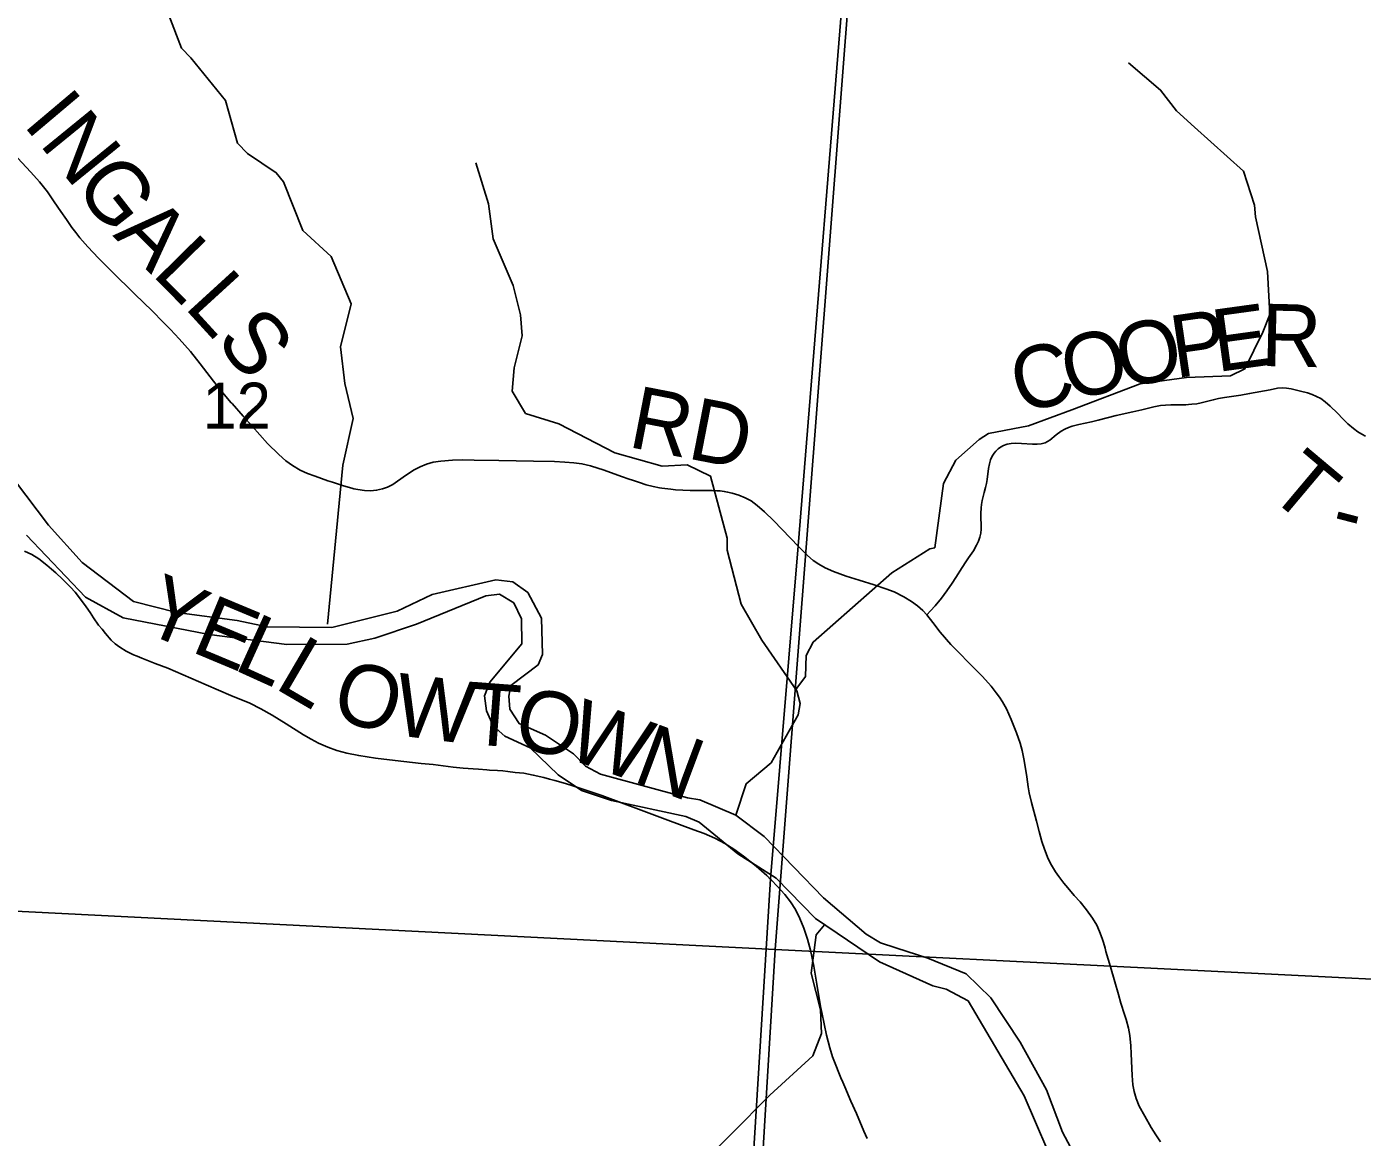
# Model space of a CAD drawing. Extents: x 396.2 to 468.4, y 232.6 to 279.1.
# Drawn here: x 420.064 to 421.28, y 275.126 to 276.138 of the extents above; entities that cross this region are included whole.
import ezdxf

# ---------------------------------------------------------------- set-up
doc = ezdxf.new("R2010")
doc.units = 0
for name, color, linetype in [('GM_X_County_Road', 7, 'Continuous'), ('GM_X_County_Road_Text', 7, 'Continuous'), ('GM_X_Major_River', 7, 'Continuous'), ('GM_X_Minor_River', 7, 'Continuous'), ('GM_X_Section', 7, 'Continuous'), ('GM_X_Section_Text', 7, 'Continuous'), ('GM_X_Township', 7, 'Continuous'), ('GM_X_Township_Road', 7, 'Continuous'), ('GM_X_Township_Road_Text', 7, 'Continuous')]:
    doc.layers.add(name, color=color, linetype=linetype)

msp = doc.modelspace()

# ---------------------------------------------------------------- linework, layer by layer
at = {"layer": 'GM_X_County_Road'}
for points in [[(420.2507, 275.7942), (420.25, 275.7949), (420.2435, 275.8024), (420.2338, 275.8145), (420.2217, 275.8303), (420.2128, 275.8415), (420.2026, 275.8532), (420.1945, 275.8617), (420.188, 275.8685), (420.1779, 275.8786), (420.1623, 275.8938), (420.141, 275.9147), (420.1292, 275.9266), (420.1194, 275.937), (420.112, 275.9453), (420.1084, 275.9501), (420.1048, 275.9546), (420.0998, 275.9618), (420.0948, 275.9691), (420.0886, 275.9781), (420.0826, 275.9871), (420.0754, 275.9962), (420.0675, 276.0051), (420.0552, 276.0182)], [(420.7664, 275.664), (420.744, 275.6874), (420.7356, 275.6957), (420.729, 275.7014), (420.7234, 275.7055), (420.7179, 275.7085), (420.7121, 275.7109), (420.7061, 275.7126), (420.7019, 275.7136), (420.6989, 275.7142), (420.6951, 275.7146), (420.6921, 275.7148), (420.6878, 275.715), (420.6853, 275.715), (420.6773, 275.7149), (420.668, 275.7149), (420.6544, 275.7157), (420.6501, 275.7161), (420.6422, 275.7172), (420.6398, 275.7176), (420.6343, 275.7187), (420.6277, 275.7203), (420.6218, 275.7222), (420.6154, 275.7243), (420.6124, 275.7253), (420.6054, 275.7279), (420.5896, 275.7336), (420.5772, 275.7376), (420.5693, 275.7394), (420.5618, 275.7403), (420.5537, 275.7408), (420.5444, 275.7413), (420.5252, 275.7419), (420.4935, 275.7424), (420.4712, 275.7427), (420.4606, 275.7429), (420.4513, 275.7427), (420.4407, 275.7419), (420.4339, 275.7408), (420.4279, 275.739), (420.4221, 275.7367), (420.4166, 275.7338), (420.4087, 275.7287), (420.3971, 275.7206), (420.3923, 275.7181), (420.3877, 275.7165), (420.3823, 275.7153), (420.3768, 275.7148), (420.3713, 275.715), (420.3653, 275.7159), (420.3616, 275.7166), (420.3599, 275.7171), (420.3521, 275.7193), (420.3421, 275.7225), (420.338, 275.7239), (420.3263, 275.728), (420.3193, 275.7306), (420.3126, 275.7337), (420.3057, 275.7377), (420.2997, 275.7421), (420.2932, 275.7478), (420.2831, 275.7579), (420.269, 275.7735), (420.2607, 275.7828), (420.2507, 275.7942)], [(421.0961, 275.1218), (421.092, 275.128), (421.0877, 275.1348), (421.0819, 275.145), (421.0768, 275.1542), (421.074, 275.1611), (421.0721, 275.1676), (421.071, 275.1736), (421.0703, 275.1822), (421.0695, 275.2019), (421.0692, 275.2093), (421.0683, 275.2186), (421.0671, 275.2253), (421.0649, 275.2331), (421.0633, 275.2378), (421.06, 275.248), (421.0578, 275.2558), (421.0545, 275.2674), (421.0506, 275.2812), (421.0465, 275.295), (421.0457, 275.298), (421.0441, 275.3032), (421.043, 275.3069), (421.0407, 275.3134), (421.0381, 275.3191), (421.0343, 275.3255), (421.0289, 275.3331), (421.023, 275.3402), (421.0176, 275.3462), (421.0147, 275.3494), (421.01, 275.3551), (421.0081, 275.3575), (421.0036, 275.3635), (421.0004, 275.3678), (420.9968, 275.3736), (420.9938, 275.3796), (420.9904, 275.3882), (420.9881, 275.3953), (420.9856, 275.4043), (420.9832, 275.4139), (420.9786, 275.4307), (420.9765, 275.4397), (420.9756, 275.4452), (420.9743, 275.4543), (420.9721, 275.4691), (420.9702, 275.4783), (420.9683, 275.4849), (420.9651, 275.4943), (420.9602, 275.5064), (420.9559, 275.5161), (420.9522, 275.5226), (420.9494, 275.5267), (420.9465, 275.5308), (420.9419, 275.5367), (420.934, 275.5455), (420.9214, 275.5584), (420.9131, 275.5668), (420.9053, 275.5748), (420.8956, 275.586), (420.8889, 275.5948), (420.8834, 275.6017), (420.8796, 275.6058), (420.8749, 275.61), (420.8694, 275.614), (420.8624, 275.6182), (420.8535, 275.6226), (420.846, 275.6256), (420.8354, 275.6292), (420.8217, 275.6333), (420.8099, 275.6371), (420.7983, 275.6414), (420.7909, 275.6447), (420.785, 275.6479), (420.7799, 275.6514), (420.7748, 275.6558), (420.7664, 275.664)]]:
    msp.add_lwpolyline(points, dxfattribs=at)
at = {"layer": 'GM_X_Major_River'}
for points in [[(420.0835, 275.6834), (420.0205, 275.7665)], [(420.8844, 275.289), (420.855, 275.2985), (420.8413, 275.3031), (420.8281, 275.311), (420.7894, 275.3439), (420.7351, 275.3998), (420.7094, 275.4194), (420.6768, 275.4334), (420.6654, 275.4352), (420.5863, 275.4566), (420.5726, 275.4638), (420.5616, 275.4751), (420.5362, 275.4921), (420.512, 275.5027), (420.5036, 275.5159), (420.5028, 275.5277), (420.5047, 275.5375), (420.5293, 275.5562), (420.5334, 275.5657), (420.5326, 275.5986), (420.52, 275.6221), (420.5064, 275.6319), (420.4909, 275.6338), (420.433, 275.6203), (420.4009, 275.6051), (420.3415, 275.5901), (420.2828, 275.5907), (420.2552, 275.5967), (420.2003, 275.6038), (420.1609, 275.6139), (420.1142, 275.6494), (420.0835, 275.6834)], [(420.0635, 275.6743), (420.1173, 275.6179), (420.1514, 275.5991), (420.2298, 275.5838), (420.3006, 275.5749), (420.3555, 275.575), (420.3808, 275.5804), (420.4187, 275.5934), (420.4818, 275.619), (420.4943, 275.6205), (420.5072, 275.6126), (420.5144, 275.5982), (420.5145, 275.5755), (420.4854, 275.5405), (420.4805, 275.528), (420.4824, 275.5143), (420.4885, 275.5007), (420.4991, 275.4913), (420.5222, 275.4807), (420.5477, 275.4561), (420.5689, 275.4418), (420.5962, 275.4328), (420.6639, 275.4182), (420.6761, 275.4129), (420.7113, 275.3842), (420.7462, 275.3619), (420.7819, 275.3253), (420.8402, 275.2856), (420.8887, 275.2638), (420.9009, 275.2609)], [(421.0288, 275.0896), (421.007, 275.1305), (420.9924, 275.1691), (420.9684, 275.2126), (420.9417, 275.253), (420.9193, 275.2748), (420.8844, 275.289)], [(420.9009, 275.2609), (420.9209, 275.2502), (420.972, 275.1636), (421.0038, 275.0895)]]:
    msp.add_lwpolyline(points, dxfattribs=at)
at = {"layer": 'GM_X_Minor_River'}
for points in [[(420.3377, 275.5934), (420.3515, 275.738), (420.361, 275.7806), (420.3535, 275.8125), (420.3493, 275.846), (420.3592, 275.8852), (420.341, 275.9281), (420.3152, 275.952), (420.2974, 275.9961), (420.291, 276.0045), (420.2648, 276.0219), (420.2557, 276.0314), (420.2448, 276.0702), (420.2133, 276.109), (420.2046, 276.1181), (420.1932, 276.1481)], [(420.8906, 275.6629), (420.8985, 275.7215), (420.9099, 275.7428), (420.9311, 275.7614), (420.9395, 275.7671), (420.9759, 275.774), (421.0153, 275.7885), (421.0775, 275.8121), (421.1199, 275.8179), (421.1598, 275.8195), (421.173, 275.8259), (421.1893, 275.8594), (421.1958, 275.8754), (421.1935, 275.9145), (421.1826, 275.9643), (421.1818, 275.975), (421.1716, 276.0058), (421.1272, 276.046), (421.1106, 276.0608), (421.0962, 276.0798), (421.067, 276.1045)], [(420.7015, 275.6715), (420.6863, 275.7281), (420.665, 275.7383), (420.6423, 275.7372), (420.5994, 275.7493), (420.5483, 275.7759), (420.518, 275.7853), (420.5058, 275.8055), (420.5077, 275.8268), (420.515, 275.856), (420.5134, 275.8751), (420.5066, 275.9017), (420.4885, 275.9442), (420.4843, 275.9762), (420.4726, 276.0134)], [(420.7015, 275.6715), (420.7016, 275.6608), (420.7144, 275.6115), (420.7332, 275.5786), (420.765, 275.5324), (420.7681, 275.521), (420.7663, 275.5108), (420.7415, 275.467), (420.7188, 275.4479), (420.7094, 275.4194)], [(420.7641, 275.5337), (420.7729, 275.5457), (420.7735, 275.5647), (420.7799, 275.5769), (420.8516, 275.6399), (420.886, 275.6618), (420.8906, 275.6629)], [(420.7901, 275.3195), (420.7827, 275.3104), (420.778, 275.2754), (420.7865, 275.242), (420.7874, 275.2204), (420.7796, 275.2002), (420.7403, 275.1643), (420.6705, 275.0937), (420.6055, 275.0482), (420.5546, 275.0039)]]:
    msp.add_lwpolyline(points, dxfattribs=at)
at = {"layer": 'GM_X_Section'}
for points in [[(419.7599, 276.357), (420.8122, 276.3213), (420.8243, 276.321), (420.7452, 275.2968), (419.7043, 275.3495)], [(420.8243, 276.321), (421.8725, 276.2694), (421.8607, 276.0303), (421.8429, 275.7758), (421.8262, 275.5154), (421.8083, 275.2473), (421.8081, 275.2441), (420.7452, 275.2968)], [(419.7043, 275.3495), (420.7452, 275.2968), (420.6845, 274.2907), (419.6431, 274.3525)], [(420.7452, 275.2968), (421.8081, 275.2441), (421.7928, 275.0058), (421.7775, 274.755), (421.761, 274.4956), (421.7452, 274.2485), (420.6845, 274.2907)]]:
    msp.add_lwpolyline(points, close=True, dxfattribs=at)
at = {"layer": 'GM_X_Township'}
for points in [[(418.0397, 276.4561), (419.5043, 276.3698), (419.7967, 276.3558), (420.5319, 276.3287), (420.82, 276.3196), (420.8133, 276.2466), (420.7662, 275.6645), (420.7409, 275.3613), (420.6691, 274.1958), (420.5899, 272.7669), (420.561, 272.2781), (420.5108, 271.2751)], [(420.6691, 274.1958), (420.7409, 275.3613), (420.7662, 275.6645), (420.8133, 276.2466), (420.82, 276.3196), (421.3281, 276.2897)]]:
    msp.add_lwpolyline(points, dxfattribs=at)
at = {"layer": 'GM_X_Township_Road'}
for points in [[(420.8834, 275.6017), (420.8868, 275.6053), (420.8909, 275.6099), (420.8968, 275.6171), (420.9016, 275.6235), (420.9065, 275.6307), (420.9099, 275.6359), (420.9155, 275.6448), (420.9189, 275.65), (420.9214, 275.6536), (420.9259, 275.6602), (420.9287, 275.6651), (420.9305, 275.669), (420.9317, 275.6725), (420.9324, 275.6762), (420.9327, 275.6799), (420.9326, 275.6941), (420.9329, 275.6991), (420.9332, 275.7022), (420.9339, 275.7058), (420.9344, 275.7083), (420.9356, 275.7131), (420.9369, 275.7179), (420.9377, 275.7215), (420.9384, 275.7252), (420.9396, 275.7351), (420.9404, 275.7393), (420.9414, 275.7429), (420.943, 275.7463), (420.9446, 275.7489), (420.9462, 275.7509), (420.9484, 275.753), (420.9504, 275.7545), (420.9531, 275.7559), (420.9566, 275.7572), (420.9603, 275.7578), (420.964, 275.758), (420.9696, 275.7578), (420.9795, 275.7571), (420.9839, 275.7572), (420.9876, 275.7576), (420.9912, 275.7586), (420.9934, 275.7596), (420.9955, 275.7609), (421.0012, 275.7657), (421.0057, 275.7691), (421.0089, 275.771), (421.0123, 275.7725), (421.0158, 275.7736), (421.0219, 275.7751), (421.0334, 275.7777), (421.037, 275.7786), (421.0394, 275.7792), (421.0557, 275.7832), (421.0709, 275.7866), (421.0793, 275.7886), (421.0902, 275.7913), (421.0963, 275.7924), (421.1006, 275.7928), (421.1056, 275.793), (421.1155, 275.793), (421.1192, 275.7931), (421.1217, 275.7933), (421.1248, 275.7936), (421.1291, 275.7941), (421.1333, 275.7949), (421.1442, 275.7975), (421.149, 275.7987), (421.1545, 275.7998), (421.1692, 275.802), (421.1772, 275.8033), (421.1961, 275.8068), (421.2028, 275.8081), (421.2071, 275.8084), (421.2108, 275.8082), (421.2151, 275.8076), (421.2236, 275.8056), (421.2301, 275.8039), (421.2342, 275.8025), (421.2382, 275.8008), (421.242, 275.7987), (421.2461, 275.7959), (421.2507, 275.7919), (421.2572, 275.7855), (421.2623, 275.7803), (421.2667, 275.7759), (421.2718, 275.7715), (421.2758, 275.7685), (421.2795, 275.7662), (421.2829, 275.7646)], [(420.7418, 275.3601), (420.7411, 275.3608), (420.7376, 275.3643), (420.7279, 275.3727), (420.7165, 275.3818), (420.7075, 275.3884), (420.6993, 275.3936), (420.6903, 275.3982), (420.6806, 275.4025), (420.6711, 275.406), (420.6475, 275.4146), (420.6232, 275.4238), (420.6052, 275.4305), (420.5873, 275.4371), (420.5593, 275.4466), (420.5521, 275.4488), (420.5447, 275.4508), (420.5398, 275.4521), (420.5345, 275.4535), (420.5249, 275.4558), (420.5164, 275.4574), (420.5085, 275.4583), (420.5017, 275.4591), (420.4974, 275.4596), (420.4925, 275.4599), (420.4851, 275.4604), (420.4827, 275.4606), (420.4752, 275.4611), (420.4703, 275.4614), (420.4612, 275.4621), (420.4521, 275.463), (420.4339, 275.4655), (420.4228, 275.4665), (420.3993, 275.4691), (420.3814, 275.4713), (420.366, 275.4736), (420.3551, 275.4757), (420.346, 275.4782), (420.3378, 275.4811), (420.3293, 275.485), (420.3226, 275.4886), (420.3156, 275.4924), (420.2999, 275.5024), (420.2873, 275.5104), (420.277, 275.5163), (420.2669, 275.5214), (420.2495, 275.5284), (420.227, 275.538), (420.1922, 275.5531), (420.1808, 275.5575), (420.1684, 275.5623), (420.1644, 275.564), (420.1609, 275.5653), (420.1542, 275.5687), (420.1484, 275.5723), (420.1444, 275.5754), (420.1407, 275.5788), (420.1353, 275.5847), (420.1323, 275.5886), (420.1292, 275.5925), (420.1246, 275.5991), (420.1214, 275.6038), (420.1178, 275.6091), (420.1128, 275.616), (420.1078, 275.6223), (420.1037, 275.6269), (420.0996, 275.6309), (420.0962, 275.6343), (420.0903, 275.6399), (420.0863, 275.6434), (420.082, 275.6471), (420.0747, 275.6527), (420.0684, 275.6566), (420.0618, 275.6599)], [(420.829, 275.1247), (420.8261, 275.1316), (420.8238, 275.1367), (420.8214, 275.1424), (420.8192, 275.1475), (420.8142, 275.1589), (420.8117, 275.1646), (420.8095, 275.1697), (420.8068, 275.176), (420.8051, 275.18), (420.8032, 275.1845), (420.8004, 275.1917), (420.7976, 275.1991), (420.7949, 275.2074), (420.7921, 275.2188), (420.7877, 275.2395), (420.7866, 275.245), (420.7831, 275.2652), (420.7804, 275.2818), (420.7774, 275.2962), (420.7748, 275.3064), (420.7715, 275.3164), (420.7677, 275.3253), (420.7638, 275.3333), (420.7593, 275.3405), (420.7541, 275.3471), (420.7472, 275.3547), (420.7418, 275.3601)]]:
    msp.add_lwpolyline(points, dxfattribs=at)

# ---------------------------------------------------------------- texts
at = {"layer": 'GM_X_County_Road_Text'}
for s, height, rotation, p in [('I', 0.0568, 310.1619, (420.0594, 276.0486)), ('N', 0.0568, 309.1815, (420.0743, 276.0309)), ('G', 0.0568, 307.9566, (420.1057, 275.9924)), ('A', 0.0568, 315.0572, (420.1415, 275.9472)), ('L', 0.0568, 314.6167, (420.1768, 275.912)), ('L', 0.0568, 312.4173, (420.2063, 275.8822)), ('S', 0.0568, 309.6705, (420.2345, 275.8513)), ('RD', 0.05682, 348.9822, (420.6101, 275.755))]:
    msp.add_text(s, height=height, rotation=rotation, dxfattribs=at).set_placement(p)
at = {"layer": 'GM_X_Section_Text'}
msp.add_text('12', height=0.04186, rotation=0, dxfattribs=at).set_placement((420.2238, 275.7714))
at = {"layer": 'GM_X_Township_Road_Text'}
for s, rotation, p in [('E', 7.848, (421.1475, 275.8228)), ('R', 358.7197, (421.1873, 275.8285)), ('O', 11.0106, (421.0613, 275.8079)), ('P', 8.2655, (421.1097, 275.8173)), ('O', 13.1448, (421.0132, 275.7966)), ('C', 15.1618, (420.9687, 275.7845)), ('T', 319.9519, (421.1919, 275.7122)), ('-', 345.4327, (421.2487, 275.6723)), ('Y', 337.4034, (420.1658, 275.588)), ('E', 337.3228, (420.212, 275.5688)), ('L', 335.5532, (420.2507, 275.5526)), ('L', 329.6834, (420.2881, 275.5357)), ('O', 344.1316, (420.3391, 275.5082)), ('W', 352.8935, (420.3965, 275.4926)), ('T', 355.6405, (420.4648, 275.4842)), ('O', 349.1734, (420.5055, 275.4812)), ('W', 340.6512, (420.5524, 275.4723)), ('N', 339.536, (420.6143, 275.4506))]:
    msp.add_text(s, height=0.0568, rotation=rotation, dxfattribs=at).set_placement(p)

doc.saveas('drawing.dxf')
